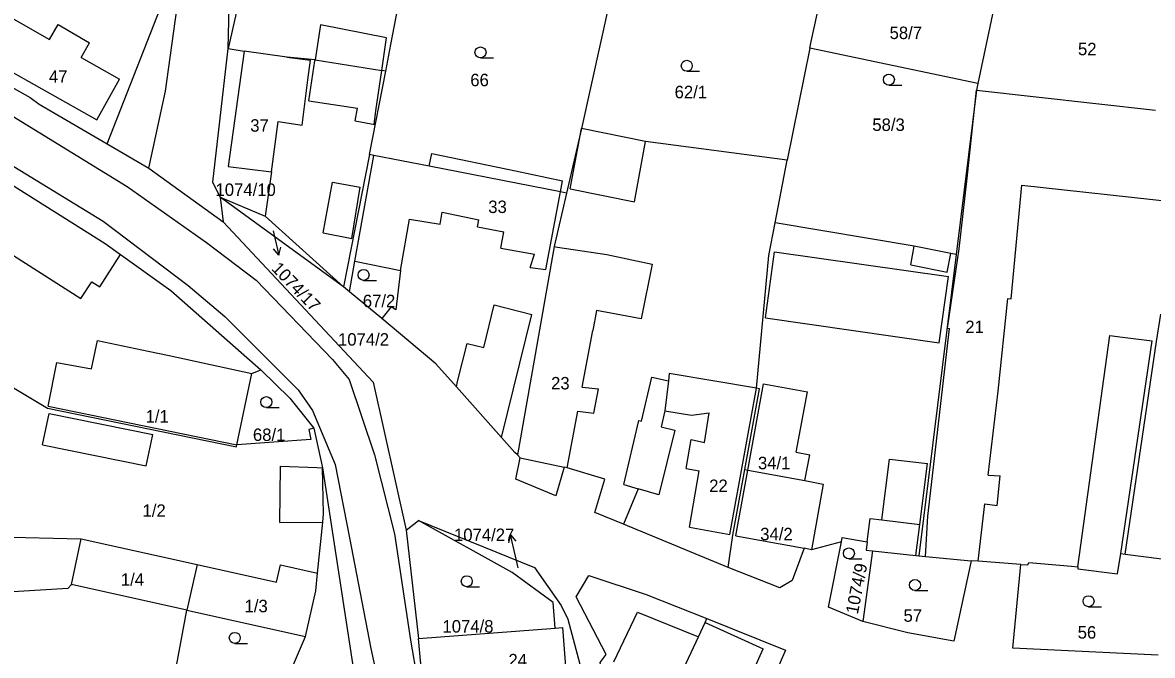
# Model space of a CAD drawing. Extents: x -746176 to -739709, y -1128407 to -1124482.
# Drawn here: x -742377 to -742223, y -1126052.3 to -1125966 of the extents above; entities that cross this region are included whole.
import ezdxf

# ---------------------------------------------------------------- set-up
doc = ezdxf.new("R2010")
doc.units = 0
for name, color, linetype in [('Vrstva 33', 7, 'Continuous'), ('Vrstva 42', 7, 'Continuous'), ('Vrstva 43', 7, 'Continuous'), ('Vrstva 44', 7, 'Continuous'), ('Vrstva 47', 7, 'Continuous')]:
    doc.layers.add(name, color=color, linetype=linetype)

msp = doc.modelspace()

# ---------------------------------------------------------------- linework, layer by layer
at = {"layer": 'Vrstva 33'}
for p, q in [((-742296.81, -1125962.38), (-742300.78, -1125980.44)), ((-742244.64, -1125964.23), (-742246.75, -1125974.33)), ((-742348.95, -1125969.57), (-742346.78, -1125969.9)), ((-742269.67, -1125969.51), (-742272.76, -1125984.75)), ((-742246.75, -1125974.33), (-742269.67, -1125969.51)), ((-742329.7, -1125984.02), (-742327.47, -1125972.62)), ((-742246.75, -1125974.33), (-742246.94, -1125975.25)), ((-742246.94, -1125975.25), (-742249.72, -1125997.65)), ((-742246.94, -1125975.25), (-742222.55, -1125977.95)), ((-742300.78, -1125980.44), (-742302.83, -1125989.25)), ((-742329.7, -1125984.02), (-742333.21, -1126002.03)), ((-742274.38, -1125993.3), (-742272.76, -1125984.75)), ((-742350.03, -1125989.81), (-742343.92, -1125992.41)), ((-742333.21, -1126002.03), (-742350.03, -1125989.81)), ((-742350.03, -1125989.81), (-742349.63, -1125993.16)), ((-742343.92, -1125992.41), (-742333.21, -1126002.03)), ((-742275.24, -1125997.79), (-742274.38, -1125993.3)), ((-742276.95, -1126015.87), (-742275.24, -1125997.79)), ((-742249.72, -1125997.65), (-742254.82, -1126038.74)), ((-742332.39, -1126002.71), (-742333.21, -1126002.03)), ((-742327.99, -1126006.38), (-742332.39, -1126002.71)), ((-742337.26, -1126021.33), (-742336.07, -1126026.71)), ((-742336.07, -1126026.71), (-742330.17, -1126065.29)), ((-742324.67, -1126035.23), (-742323.01, -1126033.89)), ((-742280.77, -1126040.3), (-742295.06, -1126034.41)), ((-742324.67, -1126035.23), (-742323.01, -1126050.01)), ((-742265.36, -1126036.8), (-742269.44, -1126037.88)), ((-742261.12, -1126038.05), (-742262.44, -1126047.69)), ((-742226.7, -1126038.48), (-742221.69, -1126039.15)), ((-742353.18, -1126039.91), (-742354.56, -1126046.13)), ((-742354.56, -1126046.13), (-742370.32, -1126042.62)), ((-742356, -1126053.72), (-742354.56, -1126046.13)), ((-742354.56, -1126046.13), (-742338.41, -1126049.72)), ((-742323.01, -1126050.01), (-742304.36, -1126048.56)), ((-742341.65, -1126057.29), (-742338.41, -1126049.72))]:
    msp.add_line(p, q, dxfattribs=at)
for points in [[(-742348.95, -1125969.57), (-742348.77, -1125961.93), (-742341.73, -1125932.77)], [(-742345.34, -1125953.5), (-742347.31, -1125962.26), (-742348.95, -1125969.57)], [(-742365.43, -1125982.55), (-742356.37, -1125959.31), (-742357.41, -1125958.73)], [(-742327.47, -1125972.62), (-742326.77, -1125969.01), (-742324.69, -1125958.1)], [(-742269.67, -1125969.51), (-742269.48, -1125968.58), (-742268.65, -1125964.88)], [(-742392.86, -1125966.72), (-742375.94, -1125976.23), (-742374.7, -1125977.14), (-742365.43, -1125982.55)], [(-742327.47, -1125972.62), (-742328.01, -1125972.53), (-742327.37, -1125968.09), (-742336.35, -1125966.33), (-742337.09, -1125971.11), (-742340.95, -1125970.71), (-742346.78, -1125969.9)], [(-742350.03, -1125989.81), (-742351.04, -1125987.76), (-742348.95, -1125969.57)], [(-742346.78, -1125969.9), (-742348.93, -1125985.62), (-742343.03, -1125986.37), (-742343.92, -1125992.41)], [(-742272.76, -1125984.75), (-742292.04, -1125982.23), (-742300.78, -1125980.44)], [(-742365.43, -1125982.55), (-742359.74, -1125985.87), (-742349.63, -1125993.16)], [(-742302.83, -1125989.25), (-742303.65, -1125989.09), (-742321.55, -1125985.61), (-742329.11, -1125984.14), (-742329.7, -1125984.02)], [(-742380.97, -1125986.53), (-742365.73, -1125996.13), (-742363.63, -1125997.63), (-742356.74, -1126002.55), (-742344.5, -1126013.38)], [(-742302.83, -1125989.25), (-742304.53, -1125996.56), (-742309.51, -1126024.97)], [(-742349.63, -1125993.16), (-742329.2, -1126015.02), (-742324.67, -1126035.23)], [(-742249.72, -1125997.65), (-742250.44, -1125997.51), (-742255.43, -1125996.5), (-742274.38, -1125993.3)], [(-742332.39, -1126002.71), (-742331.66, -1125998.55), (-742325.47, -1125999.83), (-742326.09, -1126005.17), (-742326.73, -1126004.75), (-742327.99, -1126006.38)], [(-742394.08, -1126006.45), (-742377.42, -1126016.26), (-742373.55, -1126018.6), (-742347.83, -1126023.87), (-742347.76, -1126023.57)], [(-742309.51, -1126024.97), (-742309.85, -1126024.64), (-742311.67, -1126022.6), (-742317.81, -1126015.69), (-742320.62, -1126012.53), (-742327.99, -1126006.38)], [(-742226.7, -1126038.48), (-742222.39, -1126009.48), (-742221.81, -1126005.78)], [(-742347.76, -1126023.57), (-742345.71, -1126013.84), (-742344.5, -1126013.38)], [(-742344.5, -1126013.38), (-742340.52, -1126017.22), (-742337.26, -1126021.33)], [(-742276.95, -1126015.87), (-742288.82, -1126013.86), (-742288.94, -1126014.86), (-742289.42, -1126018.96), (-742289.94, -1126021.12), (-742288.05, -1126021.59), (-742290.26, -1126030.39), (-742293.05, -1126029.57), (-742295.06, -1126034.41)], [(-742278.52, -1126026.95), (-742276.54, -1126015.94), (-742276.95, -1126015.87)], [(-742337.26, -1126021.33), (-742337.97, -1126021.51), (-742337.68, -1126022.88), (-742347.76, -1126023.57)], [(-742295.06, -1126034.41), (-742298.95, -1126032.8), (-742297.59, -1126028.26), (-742302.72, -1126026.73), (-742303.16, -1126026.63), (-742304.27, -1126030.53), (-742309.75, -1126028.26), (-742309.14, -1126025.34), (-742309.51, -1126024.97)], [(-742336.75, -1126041.07), (-742336.05, -1126034.11), (-742335.93, -1126032.98), (-742336.07, -1126026.71)], [(-742280.77, -1126040.3), (-742280.14, -1126035.91), (-742278.52, -1126026.95)], [(-742278.52, -1126026.95), (-742278.1, -1126027.02), (-742270.33, -1126028.47), (-742267.82, -1126028.93), (-742269.44, -1126037.88)], [(-742304.36, -1126048.56), (-742304.63, -1126045.08), (-742310.25, -1126041.01), (-742323.01, -1126033.89)], [(-742323.01, -1126033.89), (-742307.21, -1126040.31), (-742303.55, -1126045.47), (-742302.63, -1126047.36), (-742301.01, -1126053.5), (-742299.94, -1126062.42)], [(-742265.36, -1126036.8), (-742265.25, -1126036.21), (-742261.83, -1126036.83), (-742261.97, -1126037.96), (-742261.12, -1126038.05)], [(-742370.32, -1126042.62), (-742368.99, -1126036.39), (-742353.18, -1126039.91)], [(-742269.44, -1126037.88), (-742270.44, -1126037.69), (-742272.05, -1126042.07), (-742273.73, -1126043.08), (-742280.77, -1126040.3)], [(-742262.44, -1126047.69), (-742267.12, -1126045.73), (-742265.36, -1126036.8)], [(-742247.69, -1126039.39), (-742250.03, -1126050.34), (-742256.28, -1126049.23), (-742262.44, -1126047.69)], [(-742261.12, -1126038.05), (-742255.21, -1126038.69), (-742254.82, -1126038.74)], [(-742254.82, -1126038.74), (-742253.91, -1126038.83), (-742247.69, -1126039.39)], [(-742240.91, -1126039.92), (-742246.7, -1126039.43), (-742247.69, -1126039.39)], [(-742240.91, -1126039.92), (-742239.93, -1126039.95), (-742239.83, -1126039.64), (-742234.01, -1126040.12), (-742233.11, -1126040.21), (-742233.15, -1126040.51), (-742227.7, -1126041.18), (-742227.29, -1126038.4), (-742226.7, -1126038.48)], [(-742353.18, -1126039.91), (-742342.34, -1126042.31), (-742341.81, -1126039.93), (-742336.75, -1126041.07)], [(-742222.2, -1126052.27), (-742242, -1126051.32), (-742240.91, -1126039.92)], [(-742338.41, -1126049.72), (-742336.99, -1126043.5), (-742336.75, -1126041.07)], [(-742293.29, -1126066.63), (-742294.4, -1126065.54), (-742295.46, -1126063.33), (-742297.55, -1126057.25), (-742298.22, -1126053.27), (-742297.41, -1126052.17), (-742301.53, -1126044.31), (-742299.77, -1126041.41), (-742291.99, -1126043.99), (-742283.72, -1126047.27)], [(-742370.32, -1126042.62), (-742370.8, -1126043.17), (-742380.56, -1126043.75), (-742380.73, -1126046.24)], [(-742304.36, -1126048.56), (-742303.36, -1126048.48), (-742302.98, -1126053.8), (-742302.95, -1126054.3), (-742299.94, -1126062.42)], [(-742293.29, -1126066.63), (-742290.54, -1126062.33), (-742288.73, -1126063.39), (-742289.27, -1126059.25), (-742288.22, -1126056.95), (-742284.85, -1126049.74), (-742283.92, -1126047.8), (-742283.72, -1126047.27)], [(-742283.72, -1126047.27), (-742272.96, -1126051.59), (-742278.82, -1126065.11), (-742280.26, -1126067.67), (-742280.55, -1126068.19), (-742283.01, -1126072.54), (-742293.29, -1126066.63)], [(-742314.1, -1126079.89), (-742322.45, -1126055.94), (-742323.01, -1126050.01)]]:
    msp.add_lwpolyline(points, dxfattribs=at)
at = {"layer": 'Vrstva 43'}
for p, q in [((-742342.81, -1125994.4), (-742342.72, -1125994.81)), ((-742342.72, -1125994.81), (-742342.05, -1125997.73)), ((-742342.05, -1125997.73), (-742342.76, -1125996.87)), ((-742342.05, -1125997.73), (-742341.78, -1125996.65)), ((-742310.45, -1126035.85), (-742310.72, -1126036.93)), ((-742309.78, -1126038.77), (-742310.45, -1126035.85)), ((-742310.45, -1126035.85), (-742309.74, -1126036.71)), ((-742309.4, -1126040.35), (-742309.78, -1126038.77))]:
    msp.add_line(p, q, dxfattribs=at)
at = {"layer": 'Vrstva 44'}
for p, q in [((-742314.55, -1125970.83), (-742312.8, -1125970.83)), ((-742286.43, -1125972.66), (-742284.68, -1125972.66)), ((-742258.89, -1125974.54), (-742257.14, -1125974.54)), ((-742330.49, -1126001.16), (-742328.74, -1126001.16)), ((-742343.74, -1126018.51), (-742341.99, -1126018.51)), ((-742264.34, -1126039.14), (-742262.59, -1126039.14)), ((-742316.42, -1126042.93), (-742314.67, -1126042.93)), ((-742255.33, -1126043.44), (-742253.58, -1126043.44)), ((-742231.67, -1126045.65), (-742229.92, -1126045.65)), ((-742348.04, -1126050.65), (-742346.29, -1126050.65))]:
    msp.add_line(p, q, dxfattribs=at)
for centre in [(-742314.55, -1125970.08), (-742286.43, -1125971.91), (-742258.89, -1125973.79), (-742330.49, -1126000.41), (-742343.74, -1126017.76), (-742264.34, -1126038.39), (-742316.42, -1126042.18), (-742255.33, -1126042.69), (-742231.67, -1126044.9), (-742348.04, -1126049.9)]:
    msp.add_circle(centre, 0.75, dxfattribs=at)
at = {"layer": 'Vrstva 47'}
for p, q in [((-742357.49, -1125975.36), (-742355.32, -1125959.9)), ((-742384.05, -1125962.22), (-742373.29, -1125968.32)), ((-742373.29, -1125968.32), (-742372.12, -1125966.26)), ((-742372.12, -1125966.26), (-742367.86, -1125968.77)), ((-742387.23, -1125967.82), (-742366.83, -1125979.29)), ((-742368.99, -1125970.76), (-742367.86, -1125968.77)), ((-742368.99, -1125970.76), (-742363.74, -1125973.74)), ((-742340.95, -1125970.71), (-742337.72, -1125971.14)), ((-742338.07, -1125973.8), (-742337.72, -1125971.14)), ((-742337.96, -1125976.7), (-742337.11, -1125971.22)), ((-742337.11, -1125971.22), (-742337.09, -1125971.11)), ((-742337.09, -1125971.11), (-742328.01, -1125972.53)), ((-742328.8, -1125978.06), (-742328.01, -1125972.53)), ((-742366.83, -1125979.29), (-742363.74, -1125973.74)), ((-742338.88, -1125979.98), (-742338.07, -1125973.8)), ((-742359.74, -1125985.87), (-742357.49, -1125975.36)), ((-742248.23, -1125987.21), (-742246.94, -1125975.25)), ((-742337.96, -1125976.7), (-742331.3, -1125977.68)), ((-742331.65, -1125979.39), (-742331.3, -1125977.68)), ((-742378.39, -1125978.73), (-742362.72, -1125988.35)), ((-742329.05, -1125979.9), (-742328.8, -1125978.06)), ((-742343.03, -1125986.37), (-742342.12, -1125979.52)), ((-742342.12, -1125979.52), (-742338.88, -1125979.98)), ((-742331.65, -1125979.39), (-742329.46, -1125979.82)), ((-742329.46, -1125979.82), (-742329.05, -1125979.9)), ((-742302.32, -1125988.68), (-742300.78, -1125980.44)), ((-742293.57, -1125990.45), (-742292.04, -1125982.23)), ((-742381.3, -1125983.74), (-742366, -1125993.07)), ((-742321.55, -1125985.61), (-742321.2, -1125983.86)), ((-742321.2, -1125983.86), (-742309.76, -1125986.21)), ((-742331.66, -1125998.55), (-742329.11, -1125984.14)), ((-742309.76, -1125986.21), (-742303.37, -1125987.59)), ((-742362.72, -1125988.35), (-742351.88, -1125995.99)), ((-742335.98, -1125994.7), (-742334.74, -1125987.77)), ((-742334.74, -1125987.77), (-742330.95, -1125988.45)), ((-742332.11, -1125995.44), (-742330.95, -1125988.45)), ((-742303.65, -1125989.09), (-742303.37, -1125987.59)), ((-742249.31, -1125996.84), (-742248.23, -1125987.21)), ((-742242.22, -1126003.67), (-742240.74, -1125988.18)), ((-742240.74, -1125988.18), (-742220, -1125990.44)), ((-742305.64, -1125999.67), (-742303.65, -1125989.09)), ((-742302.32, -1125988.68), (-742293.57, -1125990.45)), ((-742366, -1125993.07), (-742354.38, -1126001.86)), ((-742325.47, -1125999.83), (-742324.24, -1125992.82)), ((-742324.24, -1125992.82), (-742320.07, -1125993.48)), ((-742320.07, -1125993.48), (-742319.78, -1125991.88)), ((-742319.78, -1125991.88), (-742314.76, -1125992.93)), ((-742314.94, -1125993.84), (-742314.76, -1125992.93)), ((-742385.4, -1125993.25), (-742369.01, -1126003.63)), ((-742335.98, -1125994.7), (-742332.11, -1125995.44)), ((-742314.94, -1125993.84), (-742311.35, -1125994.55)), ((-742311.78, -1125996.77), (-742311.35, -1125994.55)), ((-742351.88, -1125995.99), (-742345.15, -1126001.12)), ((-742366.46, -1126002.04), (-742363.63, -1125997.63)), ((-742311.78, -1125996.77), (-742307.18, -1125997.57)), ((-742307.77, -1125999.4), (-742307.18, -1125997.57)), ((-742304.53, -1125996.56), (-742304.04, -1125996.64)), ((-742304.04, -1125996.64), (-742297.32, -1125997.63)), ((-742275.68, -1126006.29), (-742274.46, -1125997.29)), ((-742274.46, -1125997.29), (-742250.78, -1126000.65)), ((-742255.88, -1125999.05), (-742255.43, -1125996.5)), ((-742250.94, -1126000.04), (-742250.44, -1125997.51)), ((-742250.91, -1126007.68), (-742249.31, -1125996.84)), ((-742255.88, -1125999.05), (-742250.94, -1126000.04)), ((-742307.77, -1125999.4), (-742305.64, -1125999.67)), ((-742252.01, -1126009.69), (-742250.78, -1126000.65)), ((-742369.01, -1126003.63), (-742367.52, -1126001.35)), ((-742367.52, -1126001.35), (-742366.46, -1126002.04)), ((-742354.38, -1126001.86), (-742349.4, -1126006.1)), ((-742345.15, -1126001.12), (-742334.74, -1126011.95)), ((-742244, -1126016.27), (-742242.65, -1126003.62)), ((-742242.65, -1126003.62), (-742242.22, -1126003.67)), ((-742314.11, -1126010.3), (-742312.7, -1126004.51)), ((-742312.7, -1126004.51), (-742307.56, -1126005.82)), ((-742349.4, -1126006.1), (-742339.39, -1126016.09)), ((-742311.67, -1126022.6), (-742307.56, -1126005.82)), ((-742275.68, -1126006.29), (-742252.01, -1126009.69)), ((-742300.68, -1126015.71), (-742299.24, -1126007.99)), ((-742253.57, -1126033.31), (-742250.61, -1126007.72)), ((-742250.91, -1126007.68), (-742250.61, -1126007.72)), ((-742367.58, -1126013.2), (-742366.76, -1126009.36)), ((-742366.76, -1126009.36), (-742359.84, -1126010.83)), ((-742317.68, -1126014.95), (-742316.39, -1126009.79)), ((-742316.39, -1126009.79), (-742314.11, -1126010.3)), ((-742233.11, -1126040.21), (-742228.77, -1126008.67)), ((-742228.77, -1126008.67), (-742227.02, -1126008.89)), ((-742227.29, -1126038.4), (-742222.99, -1126009.4)), ((-742227.02, -1126008.89), (-742222.99, -1126009.4)), ((-742359.84, -1126010.83), (-742356.97, -1126011.42)), ((-742356.97, -1126011.42), (-742345.71, -1126013.84)), ((-742373.49, -1126018.3), (-742372.32, -1126012.36)), ((-742372.32, -1126012.36), (-742367.58, -1126013.2)), ((-742334.74, -1126011.95), (-742332.47, -1126014.68)), ((-742332.47, -1126014.68), (-742328.99, -1126024.95)), ((-742292.61, -1126020.36), (-742291.18, -1126014.35)), ((-742291.18, -1126014.35), (-742288.94, -1126014.86)), ((-742339.39, -1126016.09), (-742337.47, -1126018.89)), ((-742317.81, -1126015.69), (-742317.68, -1126014.95)), ((-742300.68, -1126015.71), (-742298.47, -1126015.93)), ((-742299.1, -1126019.25), (-742298.47, -1126015.93)), ((-742280.55, -1126035.82), (-742276.95, -1126015.87)), ((-742278.1, -1126027.02), (-742275.97, -1126015.26)), ((-742275.97, -1126015.26), (-742269.97, -1126016.35)), ((-742245.33, -1126027.71), (-742244, -1126016.27)), ((-742271.51, -1126024.59), (-742269.97, -1126016.35)), ((-742374.27, -1126023.57), (-742373.33, -1126019.33)), ((-742373.49, -1126018.3), (-742347.76, -1126023.57)), ((-742373.33, -1126019.33), (-742359.21, -1126022.18)), ((-742337.47, -1126018.89), (-742334.36, -1126026.25)), ((-742302.72, -1126026.73), (-742301.28, -1126018.98)), ((-742301.28, -1126018.98), (-742299.1, -1126019.25)), ((-742289.42, -1126018.96), (-742285.79, -1126019.55)), ((-742285.79, -1126019.55), (-742283.38, -1126019.23)), ((-742284.01, -1126023.25), (-742283.38, -1126019.23)), ((-742295.01, -1126028.99), (-742292.95, -1126020.28)), ((-742292.95, -1126020.28), (-742292.61, -1126020.36)), ((-742359.45, -1126023.28), (-742359.21, -1126022.18)), ((-742374.27, -1126023.57), (-742360.14, -1126026.43)), ((-742360.14, -1126026.43), (-742359.45, -1126023.28)), ((-742286.5, -1126026.79), (-742285.82, -1126022.85)), ((-742285.82, -1126022.85), (-742284.01, -1126023.25)), ((-742328.99, -1126024.95), (-742326.26, -1126035.72)), ((-742309.14, -1126025.34), (-742303.16, -1126026.63)), ((-742271.51, -1126024.59), (-742269.67, -1126024.93)), ((-742270.33, -1126028.47), (-742269.67, -1126024.93)), ((-742259.83, -1126033.82), (-742258.82, -1126025.53)), ((-742258.82, -1126025.53), (-742253.6, -1126026.15)), ((-742341.9, -1126034.19), (-742341.81, -1126026.49)), ((-742341.81, -1126026.49), (-742336.86, -1126026.68)), ((-742336.86, -1126026.68), (-742336.07, -1126026.71)), ((-742334.36, -1126026.25), (-742332.41, -1126036.26)), ((-742286.5, -1126026.79), (-742284.74, -1126027.11)), ((-742279.73, -1126036), (-742278.1, -1126027.02)), ((-742254.67, -1126034.46), (-742253.6, -1126026.15)), ((-742286.06, -1126034.83), (-742284.74, -1126027.11)), ((-742245.33, -1126027.71), (-742243.73, -1126027.81)), ((-742244.14, -1126031.87), (-742243.73, -1126027.81)), ((-742295.01, -1126028.99), (-742293.05, -1126029.57)), ((-742246.7, -1126039.43), (-742245.79, -1126031.64)), ((-742245.79, -1126031.64), (-742244.14, -1126031.87)), ((-742341.9, -1126034.19), (-742336.05, -1126034.11)), ((-742261.83, -1126036.83), (-742261.42, -1126033.63)), ((-742261.42, -1126033.63), (-742259.83, -1126033.82)), ((-742259.83, -1126033.82), (-742254.67, -1126034.46)), ((-742255.21, -1126038.69), (-742254.67, -1126034.46)), ((-742253.91, -1126038.83), (-742253.57, -1126033.31)), ((-742380.48, -1126036.11), (-742368.99, -1126036.39)), ((-742332.41, -1126036.26), (-742329.51, -1126051.35)), ((-742326.26, -1126035.72), (-742324.08, -1126050.22)), ((-742286.06, -1126034.83), (-742280.55, -1126035.82)), ((-742279.73, -1126036), (-742270.44, -1126037.69)), ((-742296.38, -1126053.19), (-742293.13, -1126046.42)), ((-742293.13, -1126046.42), (-742284.85, -1126049.74)), ((-742283.92, -1126047.8), (-742276.03, -1126051.39)), ((-742329.51, -1126051.35), (-742326.67, -1126064.04)), ((-742324.08, -1126050.22), (-742321.93, -1126062.83)), ((-742278.04, -1126055.93), (-742276.03, -1126051.39))]:
    msp.add_line(p, q, dxfattribs=at)
msp.add_lwpolyline([(-742297.32, -1125997.63), (-742291.14, -1125998.94), (-742292.67, -1126006.4), (-742298.74, -1126005.29), (-742299.24, -1126007.99)], dxfattribs=at)

# ---------------------------------------------------------------- texts
at = {"layer": 'Vrstva 42'}
for s, p in [('58/7', (-742258.79, -1125968.26)), ('52', (-742233.11, -1125970.47)), ('47', (-742373.37, -1125974.21)), ('66', (-742315.94, -1125974.69)), ('62/1', (-742288.09, -1125976.33)), ('37', (-742345.93, -1125980.89)), ('58/3', (-742261.14, -1125980.79)), ('1074/10', (-742350.67, -1125989.65)), ('33', (-742313.49, -1125991.98)), ('67/2', (-742330.59, -1126004.82)), ('21', (-742248.47, -1126008.35)), ('1074/2', (-742333.97, -1126010.06)), ('23', (-742304.93, -1126016.03)), ('1/1', (-742360.2, -1126020.55)), ('68/1', (-742345.57, -1126023.06)), ('34/1', (-742276.73, -1126026.91)), ('22', (-742283.38, -1126030.02)), ('1/2', (-742360.62, -1126033.4)), ('1074/27', (-742318.16, -1126036.7)), ('34/2', (-742276.42, -1126036.6)), ('1/4', (-742363.57, -1126042.8)), ('1/3', (-742346.71, -1126046.41)), ('57', (-742256.89, -1126047.71)), ('1074/8', (-742319.73, -1126049.18)), ('56', (-742233.15, -1126050)), ('24', (-742310.74, -1126053.79))]:
    msp.add_text(s, height=1.7, dxfattribs=at).set_placement(p)
for s, rotation, p in [('1074/17', 314, (-742343.14, -1125999.65)), ('1074/9', 79, (-742263.12, -1126046.76))]:
    msp.add_text(s, height=1.7, rotation=rotation, dxfattribs=at).set_placement(p)

doc.saveas('drawing.dxf')
